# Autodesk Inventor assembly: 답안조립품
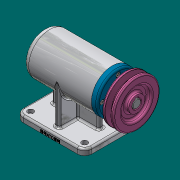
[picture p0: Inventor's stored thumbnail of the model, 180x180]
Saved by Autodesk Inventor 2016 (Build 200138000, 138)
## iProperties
Created: 2020-10
Part Number: 답안조립품
Material: 일반
Document SubType Name: Assembly
Designer: 605-12
Author: 605-12
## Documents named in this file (12)
- C:\Users\605-12\Desktop\701004V1008\답안조립품.iam
- C:\Users\605-12\Desktop\701004V1008\본체.ipt
- C:\Users\605-12\Desktop\701004V1008\커버.ipt
- C:\Users\605-12\Desktop\701004V1008\축.ipt
- C:\Users\605-12\Desktop\701004V1008\베어링 6004.ipt
- C:\Users\605-12\Desktop\701004V1008\어댑터슬리브.ipt
- C:\Users\605-12\Desktop\701004V1008\베어링 51202.ipt
- C:\Users\605-12\Desktop\701004V1008\오일 실.ipt
- C:\Users\605-12\Desktop\701004V1008\키 5 x 5 x 16.ipt
- C:\Users\605-12\Desktop\701004V1008\V벨트풀리.ipt
- C:\Users\605-12\Desktop\701004V1008\멈춤나사 M3.ipt
- C:\Users\605-12\Desktop\701004V1008\볼트 M4.ipt
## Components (1 placed, 1 different names)
1. V벨트풀리:1 — 플러쉬:5
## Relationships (1: Flush 1)
- 플러쉬:5 [Flush]: V벨트풀리:1
